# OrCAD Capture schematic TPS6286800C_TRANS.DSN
size D; title: TPS6286800C 2.4-V to 5.5-V Input, 4-A Synchronous Step-Down; rev: 1.1; note: Datasheet: SLVSFS3A        EVM: SLUUC88A
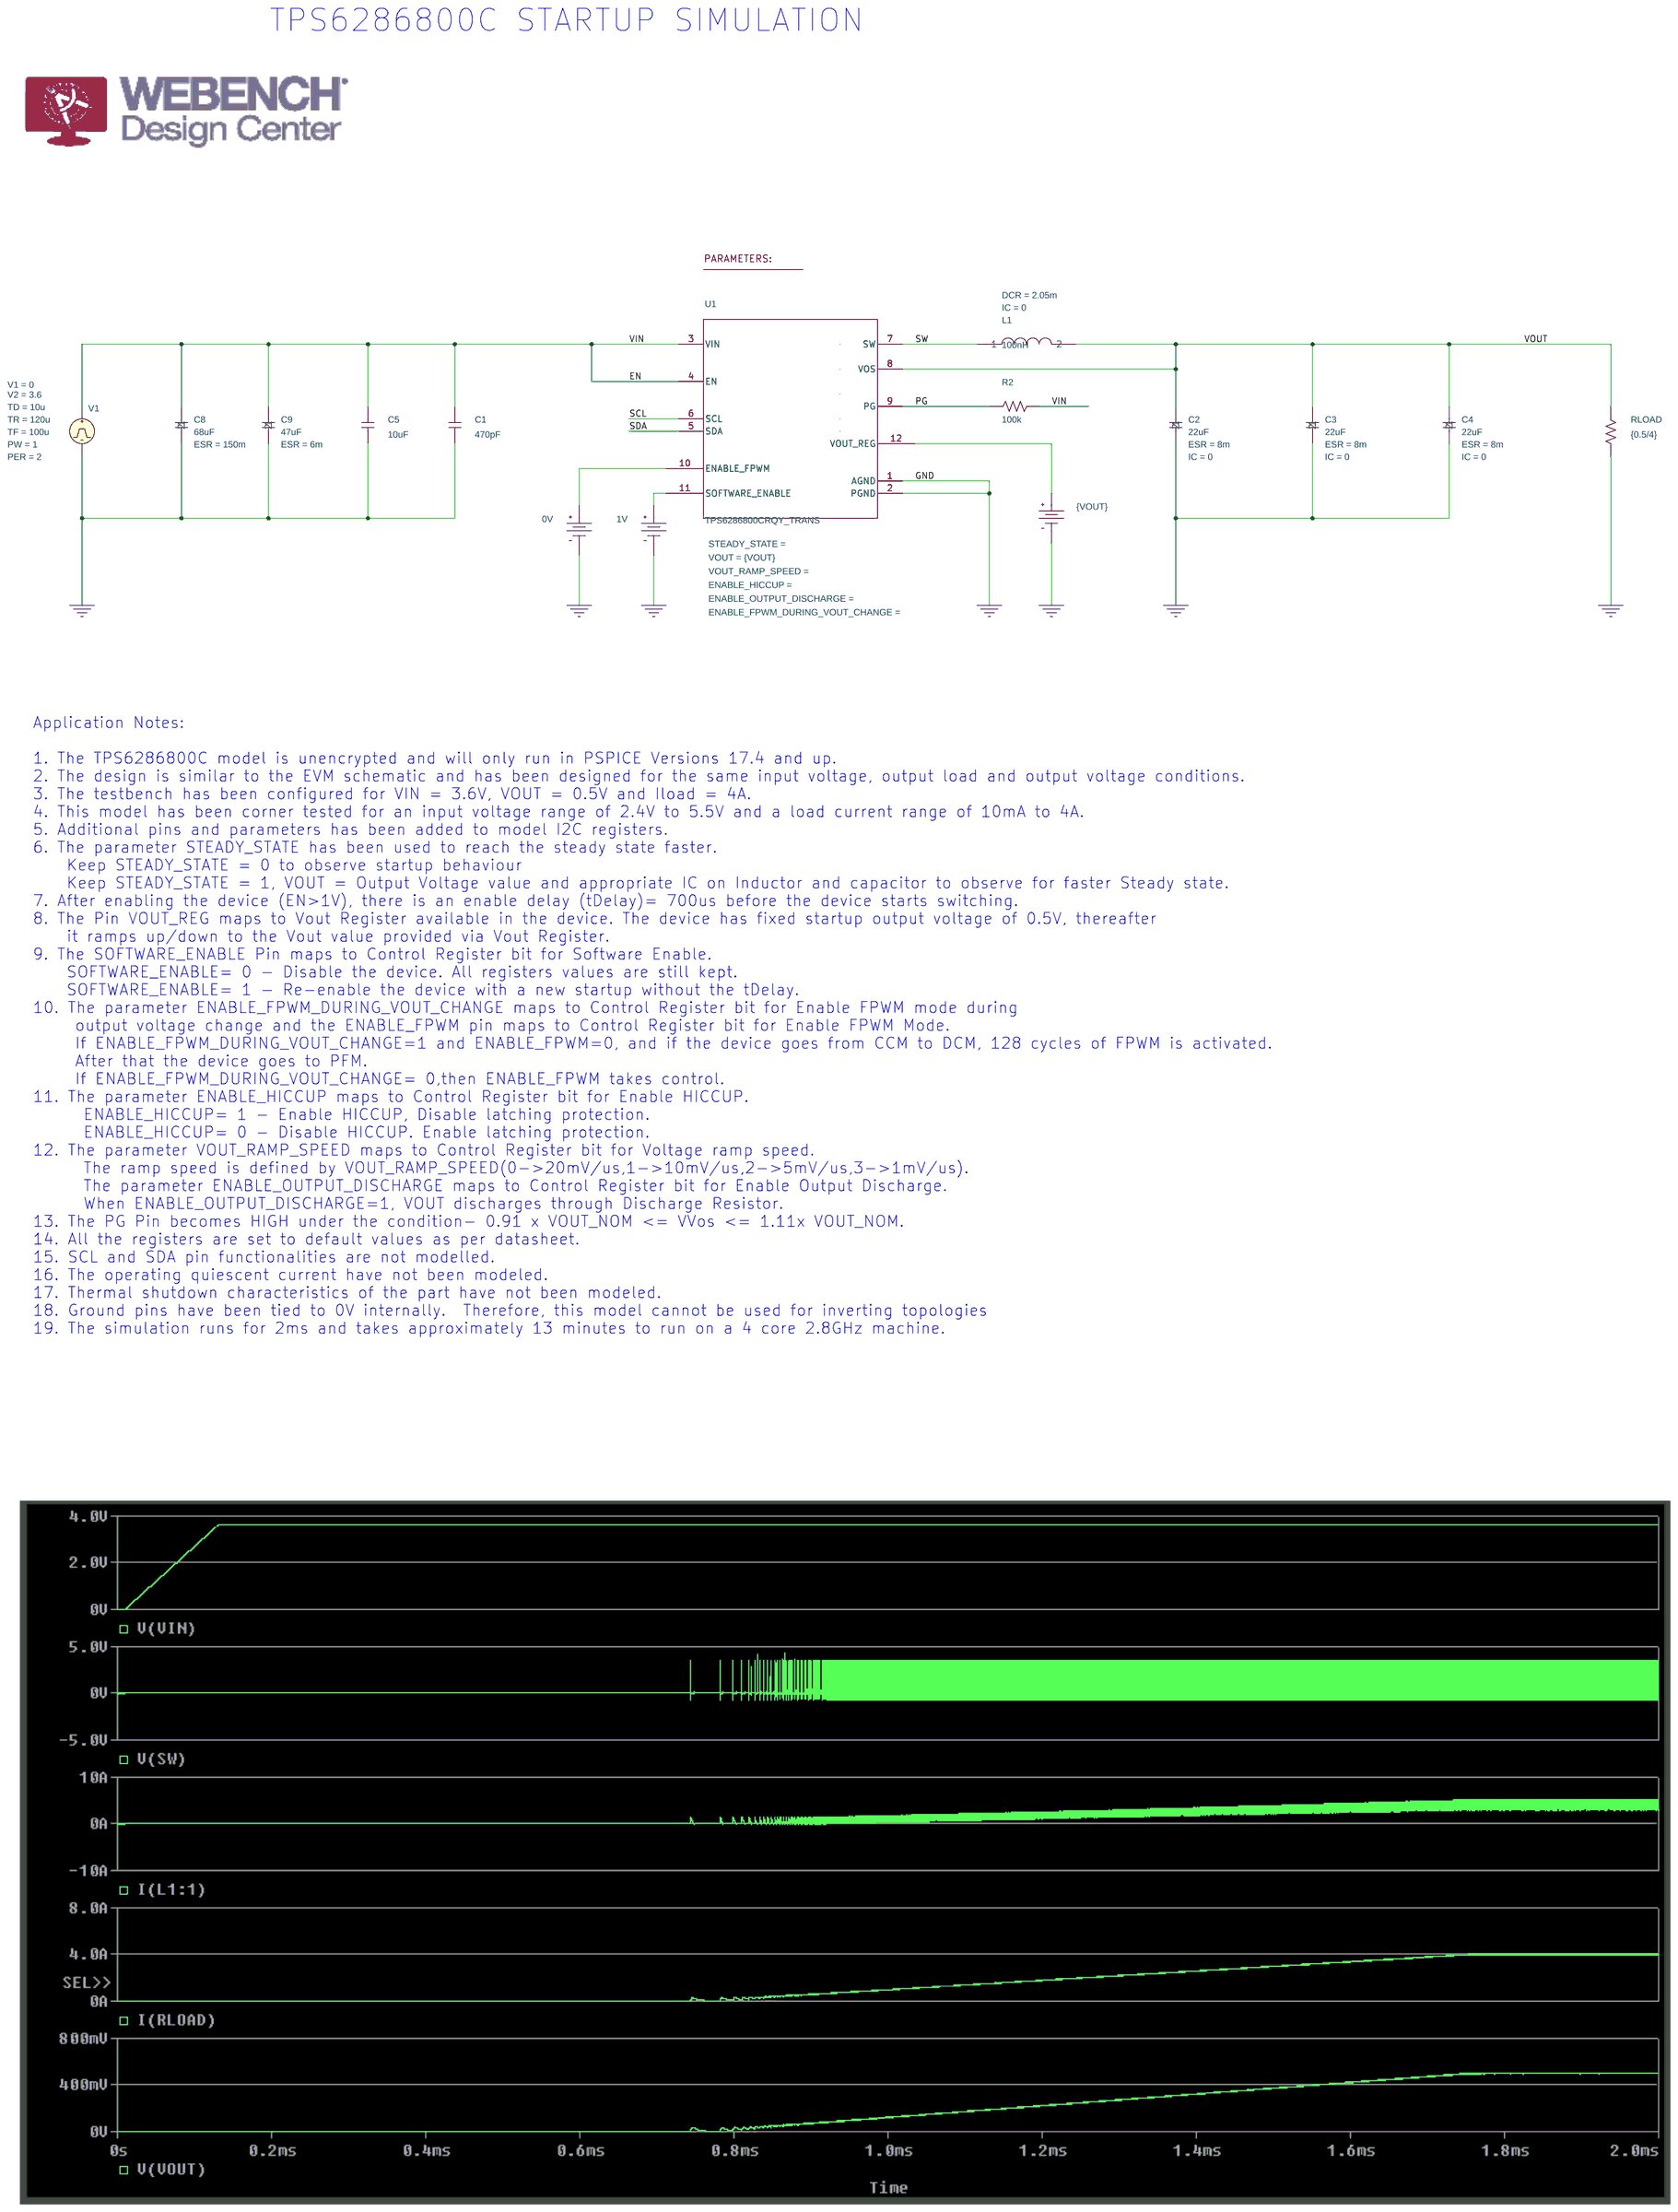
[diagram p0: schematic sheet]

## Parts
6  PARAM
C1  470pF  [RAD/CK05]
C2  CESR
C3  CESR
C4  CESR
C5  10uF  [RAD/CK05]
C8  CESR
C9  CESR
L1  LDCR
R2  100k  [AX/RC05]
RLOAD  {0.5/4}  [AX/RC05]
U1  TPS6286800CRQY_TRANS  [RQY0009A-MFG]
V1  VPULSE
V2  VDC
V3  VDC
V4  VDC

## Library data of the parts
6 = PARAM: VOUT: 0.5
C1 C5 = C
C2 = CESR_4: C: 22uF; ESL: 0; ESR: 8m; IC: 0; PSpiceTemplate: X^@REFDES %1 %2 @MODEL PARAMS: ?C|C=@C||C=10U| ?ESR|ESR=@ESR||ESR=2M| ?ESL|ESL=@ESL||ESL=1N| ?IC|IC=@IC||IC=0|
C3 = CESR_1: C: 22uF; ESL: 0; ESR: 8m; IC: 0; PSpiceTemplate: X^@REFDES %1 %2 @MODEL PARAMS: ?C|C=@C||C=10U| ?ESR|ESR=@ESR||ESR=2M| ?ESL|ESL=@ESL||ESL=1N| ?IC|IC=@IC||IC=0|
C4 = CESR: C: 22uF; ESL: 0; ESR: 8m; IC: 0; PSpiceTemplate: X^@REFDES %1 %2 @MODEL PARAMS: ?C|C=@C||C=10U| ?ESR|ESR=@ESR||ESR=2M| ?ESL|ESL=@ESL||ESL=1N| ?IC|IC=@IC||IC=0|
C8 = CESR_3: C: 68uF; ESR: 150m; PSpiceTemplate: X^@REFDES %1 %2 @MODEL PARAMS: ?C|C=@C||C=10U| ?ESR|ESR=@ESR||ESR=2M| ?ESL|ESL=@ESL||ESL=1N| ?IC|IC=@IC||IC=0|
C9 = CESR_2: C: 47uF; ESR: 6m; PSpiceTemplate: X^@REFDES %1 %2 @MODEL PARAMS: ?C|C=@C||C=10U| ?ESR|ESR=@ESR||ESR=2M| ?ESL|ESL=@ESL||ESL=1N| ?IC|IC=@IC||IC=0|
L1 = LDCR: DCR: 2.05m; IC: 0; L: 100nH
R2 RLOAD = R
U1 = TPS6286800CRQY_TRANS: VOUT: {VOUT}
V1 = VPULSE: PER: 2; PW: 1; TD: 10u; TF: 100u; TR: 120u; V1: 0; V2: 3.6
V2 = VDC: DC: 0V
V3 = VDC: DC: 1V
V4 = VDC: DC: {VOUT}

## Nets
0: C1.1 C2.2 C3.2 C4.2 C5.1 C8.2 C9.2 RLOAD.2 U1.1(AGND) U1.2(PGND) V1.2(-) V2.1(-) V3.1(-) V4.1(-)
EN: C1.2 C5.2 C8.1 C9.1 R2.2 U1.3(VIN) U1.4(EN) V1.1(+)
PG: R2.1 U1.9(PG)
SCL: U1.6(SCL)
SDA: U1.5(SDA)
SW: L1.1 U1.7(SW)
VOUT: C2.1 C3.1 C4.1 L1.2 RLOAD.1 U1.8(VOS)
N16780509: U1.11(SOFTWARE_ENABLE) V3.0(+)
N16780550: U1.10(ENABLE_FPWM) V2.0(+)
N16783455: U1.12(VOUT_REG) V4.0(+)

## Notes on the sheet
- TPS6286800C STARTUP SIMULATION
- Application Notes:
  1. The TPS6286800C model is unencrypted and will only run in PSPICE Versions 17.4 and up.
  2. The design is similar to the EVM schematic and has been designed for the same input voltage, output load and output voltage conditions.
  3. The testbench has been configured for VIN = 3.6V, VOUT = 0.5V and Iload = 4A.
  4. This model has been corner tested for an input voltage range of 2.4V to 5.5V and a load current range of 10mA to 4A.
  5. Additional pins and parameters has been added to model I2C registers.
  6. The parameter STEADY_STATE has been used to reach the steady state faster.
      Keep STEADY_STATE = 0 to observe startup behaviour
      Keep STEADY_STATE = 1, VOUT = Output Voltage value and appropriate IC on Inductor and capacitor to observe for faster Steady state.
  7. After enabling the device (EN>1V), there is an enable delay (tDelay)= 700us before the device starts switching.
  8. The Pin VOUT_REG maps to Vout Register available in the device. The device has fixed startup output voltage of 0.5V, thereafter
      it ramps up/down to the Vout value provided via Vout Register.
  9. The SOFTWARE_ENABLE Pin maps to Control Register bit for Software Enable.
      SOFTWARE_ENABLE= 0 - Disable the device. All registers values are still kept.
      SOFTWARE_ENABLE= 1 - Re-enable the device with a new startup without the tDelay.
  10. The parameter ENABLE_FPWM_DURING_VOUT_CHANGE maps to Control Register bit for Enable FPWM mode during
       output voltage change and the ENABLE_FPWM pin maps to Control Register bit for Enable FPWM Mode.
       If ENABLE_FPWM_DURING_VOUT_CHANGE=1 and ENABLE_FPWM=0, and if the device goes from CCM to DCM, 128 cycles of FPWM is activated.
       After that the device goes to PFM.
       If ENABLE_FPWM_DURING_VOUT_CHANGE= 0,then ENABLE_FPWM takes control.
  11. The parameter ENABLE_HICCUP maps to Control Register bit for Enable HICCUP.
        ENABLE_HICCUP= 1 - Enable HICCUP, Disable latching protection.
        ENABLE_HICCUP= 0 - Disable HICCUP. Enable latching protection.
  12. The parameter VOUT_RAMP_SPEED maps to Control Register bit for Voltage ramp speed.
        The ramp speed is defined by VOUT_RAMP_SPEED(0->20mV/us,1->10mV/us,2->5mV/us,3->1mV/us).
        The parameter ENABLE_OUTPUT_DISCHARGE maps to Control Register bit for Enable Output Discharge.
        When ENABLE_OUTPUT_DISCHARGE=1, VOUT discharges through Discharge Resistor.
  13. The PG Pin becomes HIGH under the condition- 0.91 x VOUT_NOM <= VVos <= 1.11x VOUT_NOM.
  14. All the registers are set to default values as per datasheet.
  15. SCL and SDA pin functionalities are not modelled.
  16. The operating quiescent current have not been modeled.
  17. Thermal shutdown characteristics of the part have not been modeled.
  18. Ground pins have been tied to 0V internally.  Therefore, this model cannot be used for inverting topologies
  19. The simulation runs for 2ms and takes approximately 13 minutes to run on a 4 core 2.8GHz machine.
